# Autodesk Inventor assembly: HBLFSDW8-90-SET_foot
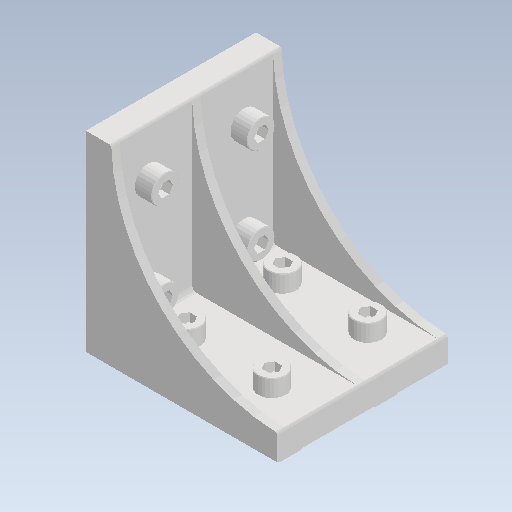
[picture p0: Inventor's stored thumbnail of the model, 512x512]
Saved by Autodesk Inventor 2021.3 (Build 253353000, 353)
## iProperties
Created: 2022-02
Part Number: HBLFSDW8-90-SET_foot
Document SubType Name: Assembly
Designer: kengo
Author: kengo
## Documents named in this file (4)
- C:\Users\kengo\Documents\frame_misumi_ver12\Anker\foot\HBLFSDW8-90-SET_foot.iam
- C:\Users\kengo\Documents\frame_misumi_ver12\Anker\foot\HBLFSDW8-90.ipt
- C:\Users\kengo\Documents\frame_misumi_ver12\Anker\foot\HNTT8-8.ipt
- C:\Users\kengo\Documents\frame_misumi_ver12\Anker\foot\SCB8-22.ipt
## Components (13 placed, 3 different names)
1. HBLFSDW8-90
2. SCB8-22
3. SCB8-22:1
4. SCB8-22:2
5. SCB8-22:3
6. HNTT8-8:4
7. SCB8-22:4
8. HNTT8-8:5
9. SCB8-22:5
10. HNTT8-8:6
11. SCB8-22:6
12. HNTT8-8:7
13. SCB8-22:7
